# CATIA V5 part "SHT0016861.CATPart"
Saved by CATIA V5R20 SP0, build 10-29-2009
Part number: SHT0016861
Bounding box of the stored display mesh (mm): x -45.13 to 52.98, y -513 to 0, z 0 to 609.926
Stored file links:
  F:\福田A6\1-数据\6-冻结数据\第三批\SHT0016861 右扶手支架总成\SHT0016861.CATPart
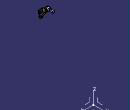
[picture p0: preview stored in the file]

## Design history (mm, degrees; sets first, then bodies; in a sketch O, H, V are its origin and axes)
AxisSystem1: origin (0, 0, 0), X (1, 0, 0), Y (0, 1, 0), Z (0, 0, 1)
Set1
  AxisLine1: Element face of Solid4
  AxisLine2: Element face of Solid4
  Rotate1: ToTransfor AxisLine1, Axis AxisLine2, Angle 90
  Plane1: type 2Lines, Element1 AxisLine2, Element2 Rotate1
  Line1: type PtDir, RefPoint {point type OnCurve, Support edge [face of Solid1 | face of Solid1], Ratio 0}, Direction edge [face of Solid1 | face of Solid1], Start 0, End 3
  Point1: type Center, Curve edge [face of Solid1 | face of Solid1]
  Plane2: type 1Line1Pt, RefPoint Point1, Line Line1
  Plane3: type 1Line1Pt, RefPoint {point type Center, Curve edge [face of Solid2 | face of Solid2]}, Line edge [face of Solid2 | face of Solid2]
Body1 (main body)
Body2 "SHT0011363 轴套"
  Solid1: solid without history
Body3 "SHT0011363 轴套"
  Solid2 "实体.1": solid without history
Body4 "焊道"
  Solid3 "实体.1": solid without history
Body5 "SHT0013120 扶手转轴"
  Solid4 "实体.3": solid without history
Body6 "SHT0014367 H6扶手支架"
  Solid5 "实体.4": solid without history
Body7 "焊道"
  Sketch1 on Plane2, origin (-198.5947, -0.0001, 489.1834), H (0, -1, 0), V (0.9266, 0, 0.3762)
    line L1 (506.0002, 244.7868) -> (503.0002, 241.7868)
    point P1 (506.0002, 244.7868)
    point P2 (503.0002, 241.7868)
    projected line E1 (503.0002, 244.7868) -> (506.0002, 244.7868) from Line1
    point P4 (506.0002, 244.7868)
    line L2 (503.0002, 244.7868) -> (503.0002, 241.7868)
    point P5 (503.0002, 241.7868)
    angle L1 L2 = 45
    coincidence: P1 P4, P2 P5
    vertical: L2 V
  Rib1: profile Sketch1, centre curve edge [face of Solid1 | face of Solid1]
  Rib2: profile Sketch1, centre curve edge [face of Solid1 | face of Solid1]
  Sketch2 on face of Solid5, origin (-0.0001, -503.0002, 0), H (1, 0, 0), V (0, 0, 1)
    line L1 (12.8351, 568.0498) -> (31.0526, 580.5964)
    line L2 (23.4601, 605.3796) -> (32.9712, 591.5697)
    reference projected point E2 (37.4799, 585.023) from Point1
    line L3 (12.8351, 568.0498) -> (65.2636, 544.6814)
    line L4 (23.4601, 605.3796) -> (66.9423, 605.3141)
    line L5 (32.9712, 591.5697) -> (44.5519, 589.8935)
    line L6 (31.0526, 580.5964) -> (41.5777, 579.0731)
    line L7 (44.5519, 589.8935) -> (66.9423, 605.3141)
    line L8 (41.5777, 579.0731) -> (65.2636, 544.6814)
    reference projected line E3 (16.3973, 575.811) -> (21.5423, 603.722) from edge [face of Solid5 | face of Solid5]
    angle L1 E3 = 45
    perpendicularity: L2 L1
    coincidence: L2 E2, L2 L8
    parallelism: L6 L5
    fix: L1
  Pocket1: profile Sketch2, direction (0, -1, 0), length 20
Body8 "焊道"
  Sketch3 on Plane3, origin (188.936, -0.0001, 465.401), H (0, -1, 0), V (-0.9266, 0, 0.3761)
    line L1 (503.0002, 164.2213) -> (503.0002, 161.2213)
    line L2 (506.0002, 164.2213) -> (503.0002, 164.2213)
    construction line L3 (506.0002, 164.2213) -> (506.0002, 157.0498)
    construction line L4 (503.0002, 164.2213) -> (506.0002, 164.2213)
    construction line L5 (503.0002, 157.0498) -> (506.0002, 157.0498)
    point P5 (506.0002, 164.2213)
    line L6 (506.0002, 164.2213) -> (503.0002, 161.2213)
    distance L1 L3 = 3
    angle L6 L1 = 45
    vertical: L1 V
    fix: L2, L1
    perpendicularity: L4 L1, L4 L3, L5 L1, L5 L3
    coincidence: L3 P5
  Rib3: profile Sketch3, centre curve edge [face of Solid2 | face of Solid2]
  Rib4: profile Sketch3, centre curve edge [face of Solid2 | face of Solid2]
  Sketch4 on face of Solid5, origin (-0.0001, -503.0002, 0), H (1, 0, 0), V (0, 0, 1)
    line L1 (60.449, 553.6201) -> (34.1442, 535.5037)
    reference projected line E1 (45.0878, 540.7922) -> (42.7526, 528.1244) from edge [face of Solid5 | face of Solid5]
    point P3 (27.5095, 530.9342)
    reference projected arc E2 centre (27.5095, 530.9342) radius 4.5 from (31.679, 529.2416) to (23.34, 532.6269) ccw from edge [face of Solid2 | face of Solid2]
    line L2 (9.9825, 556.3832) -> (23.042, 537.421)
    point P4 (9.9825, 556.3832)
    point P6 (9.9825, 556.3832)
    point P8 (21.1674, 526.5664)
    point P10 (32.1831, 524.1481)
    line L3 (21.1674, 526.5664) -> (-9.4182, 505.5018)
    line L4 (32.1831, 524.1481) -> (53.003, 493.9179)
    line L5 (23.042, 537.421) -> (34.1442, 535.5037)
    line L6 (21.1674, 526.5664) -> (32.1831, 524.1481)
    line L7 (9.9825, 556.3832) -> (60.449, 553.6201)
    line L8 (-9.4182, 505.5018) -> (53.003, 493.9179)
    angle L1 E1 = 45
    angle L2 L1 = 90
    concentricity: E2 P3
    coincidence: L1 P3, L2 P3, P6 L2, P8 L1, P10 L2, L1 L3, L2 L4, P4 P6
  Pocket2: profile Sketch4, direction (0, -1, 0), length 20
